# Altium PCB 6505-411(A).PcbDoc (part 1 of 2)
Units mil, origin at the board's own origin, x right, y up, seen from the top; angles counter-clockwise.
Board outline 1549.7 x 1971.6 mil, 4 copper layers (Top Layer, Mid-Layer 1, Mid-Layer 2, Bottom Layer); 80 components, 57 nets, 309 pads, 377 vias.
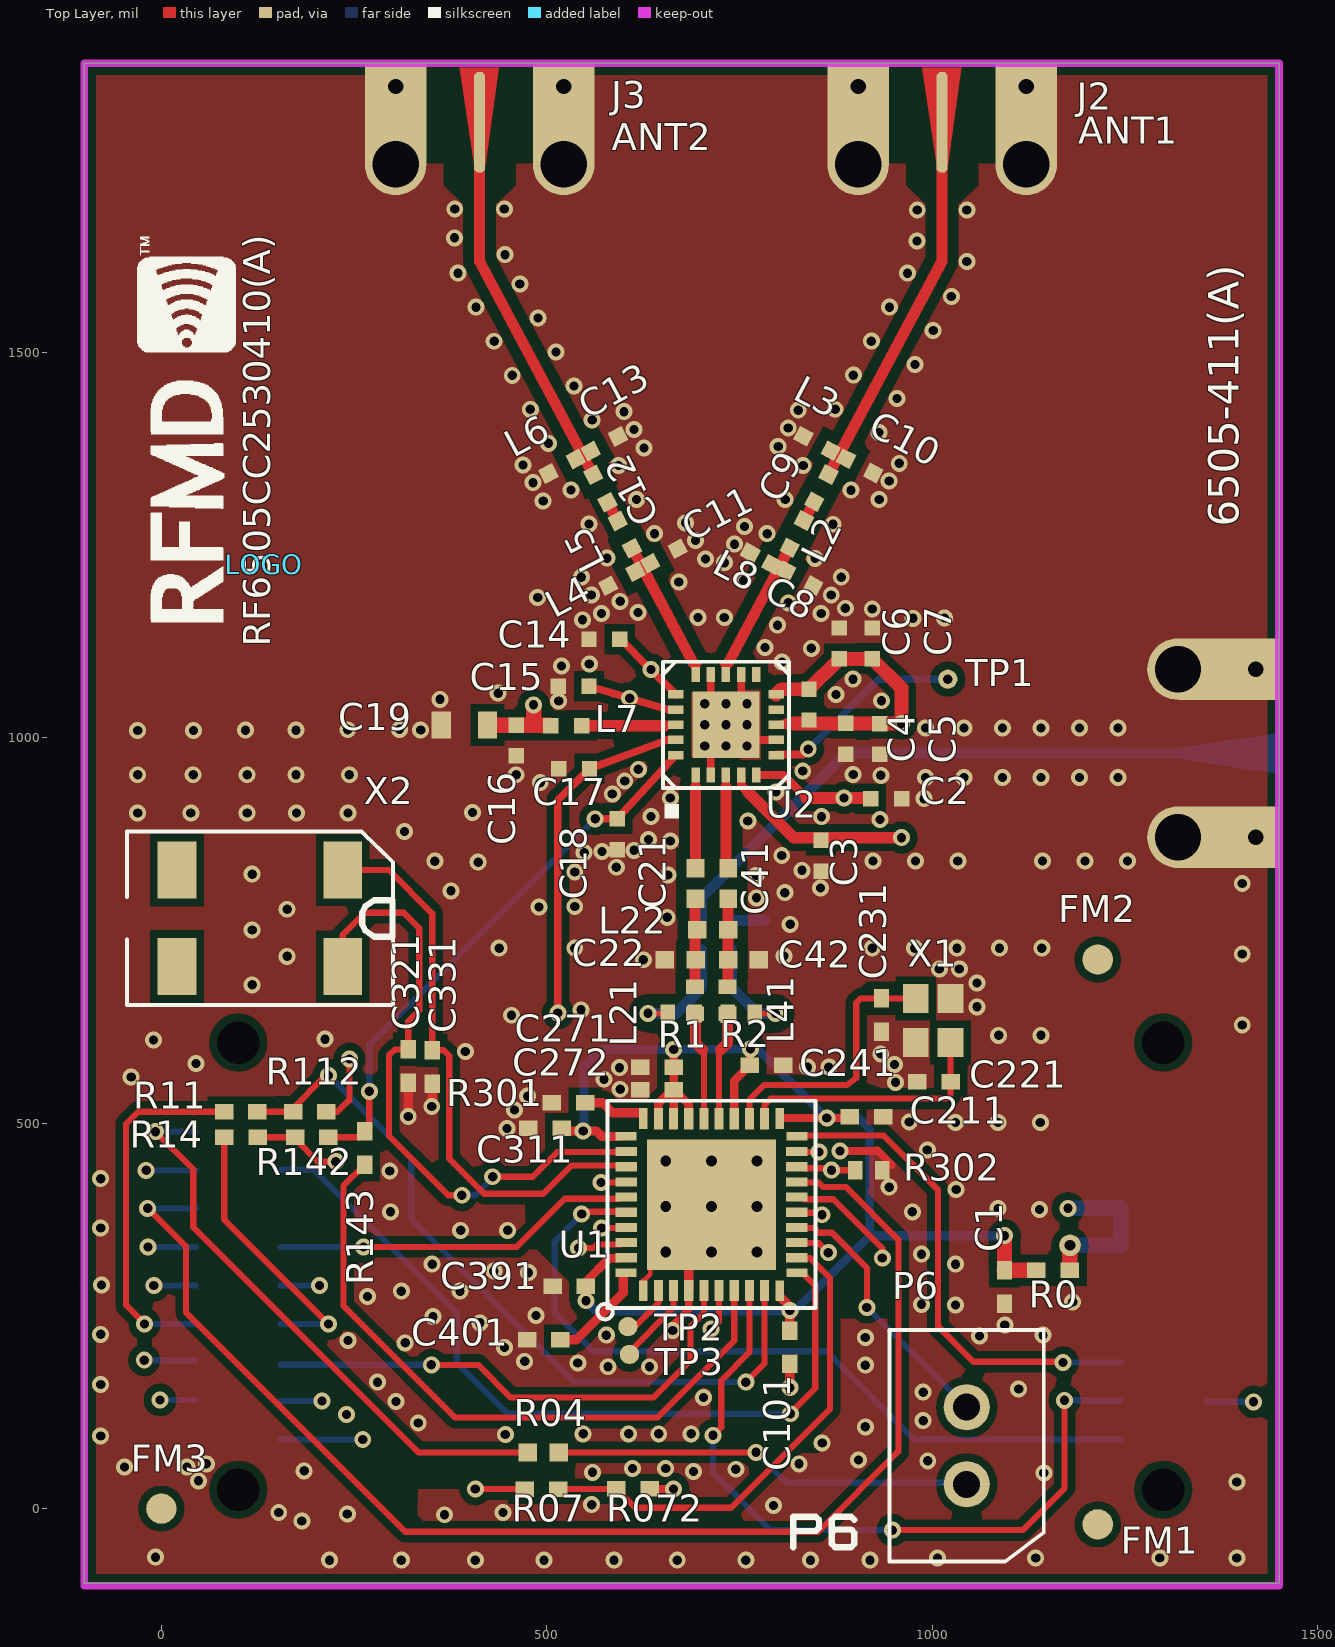
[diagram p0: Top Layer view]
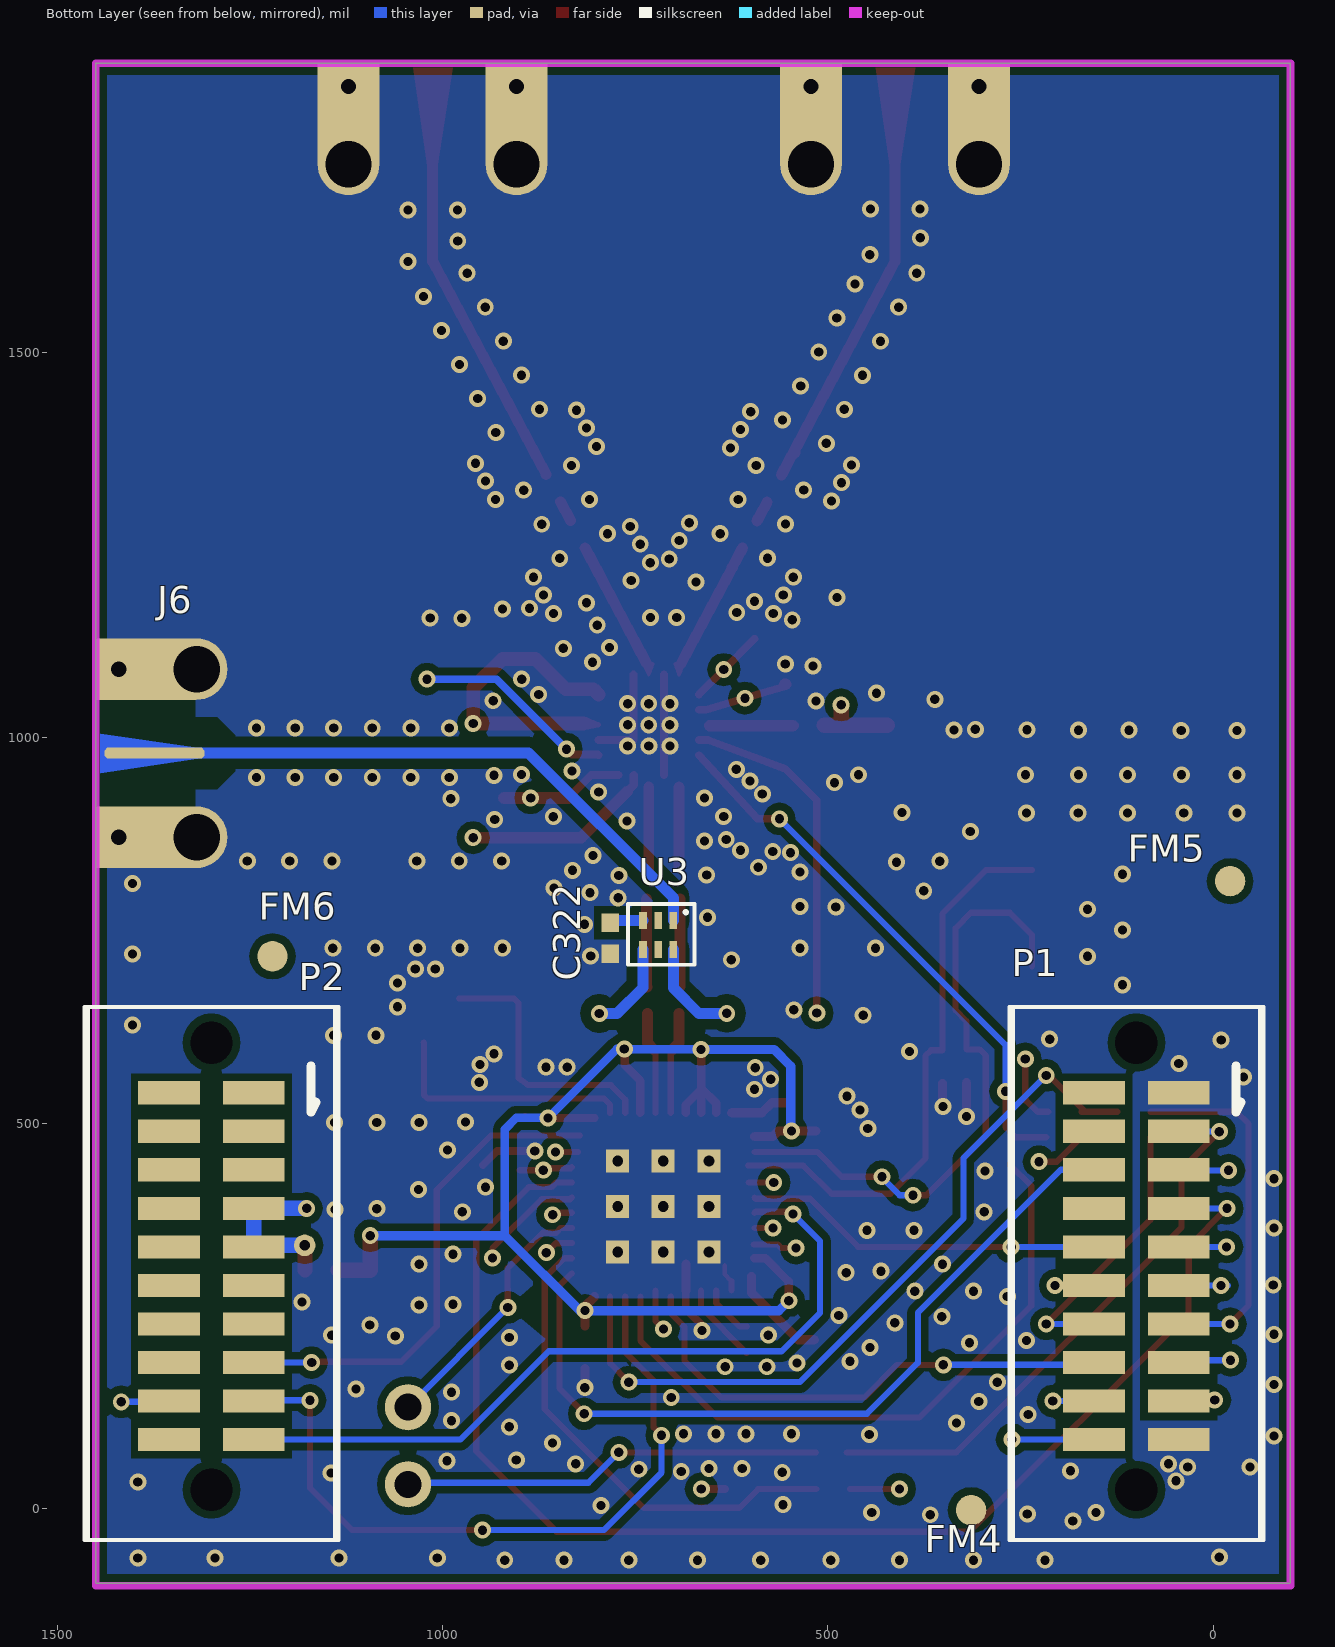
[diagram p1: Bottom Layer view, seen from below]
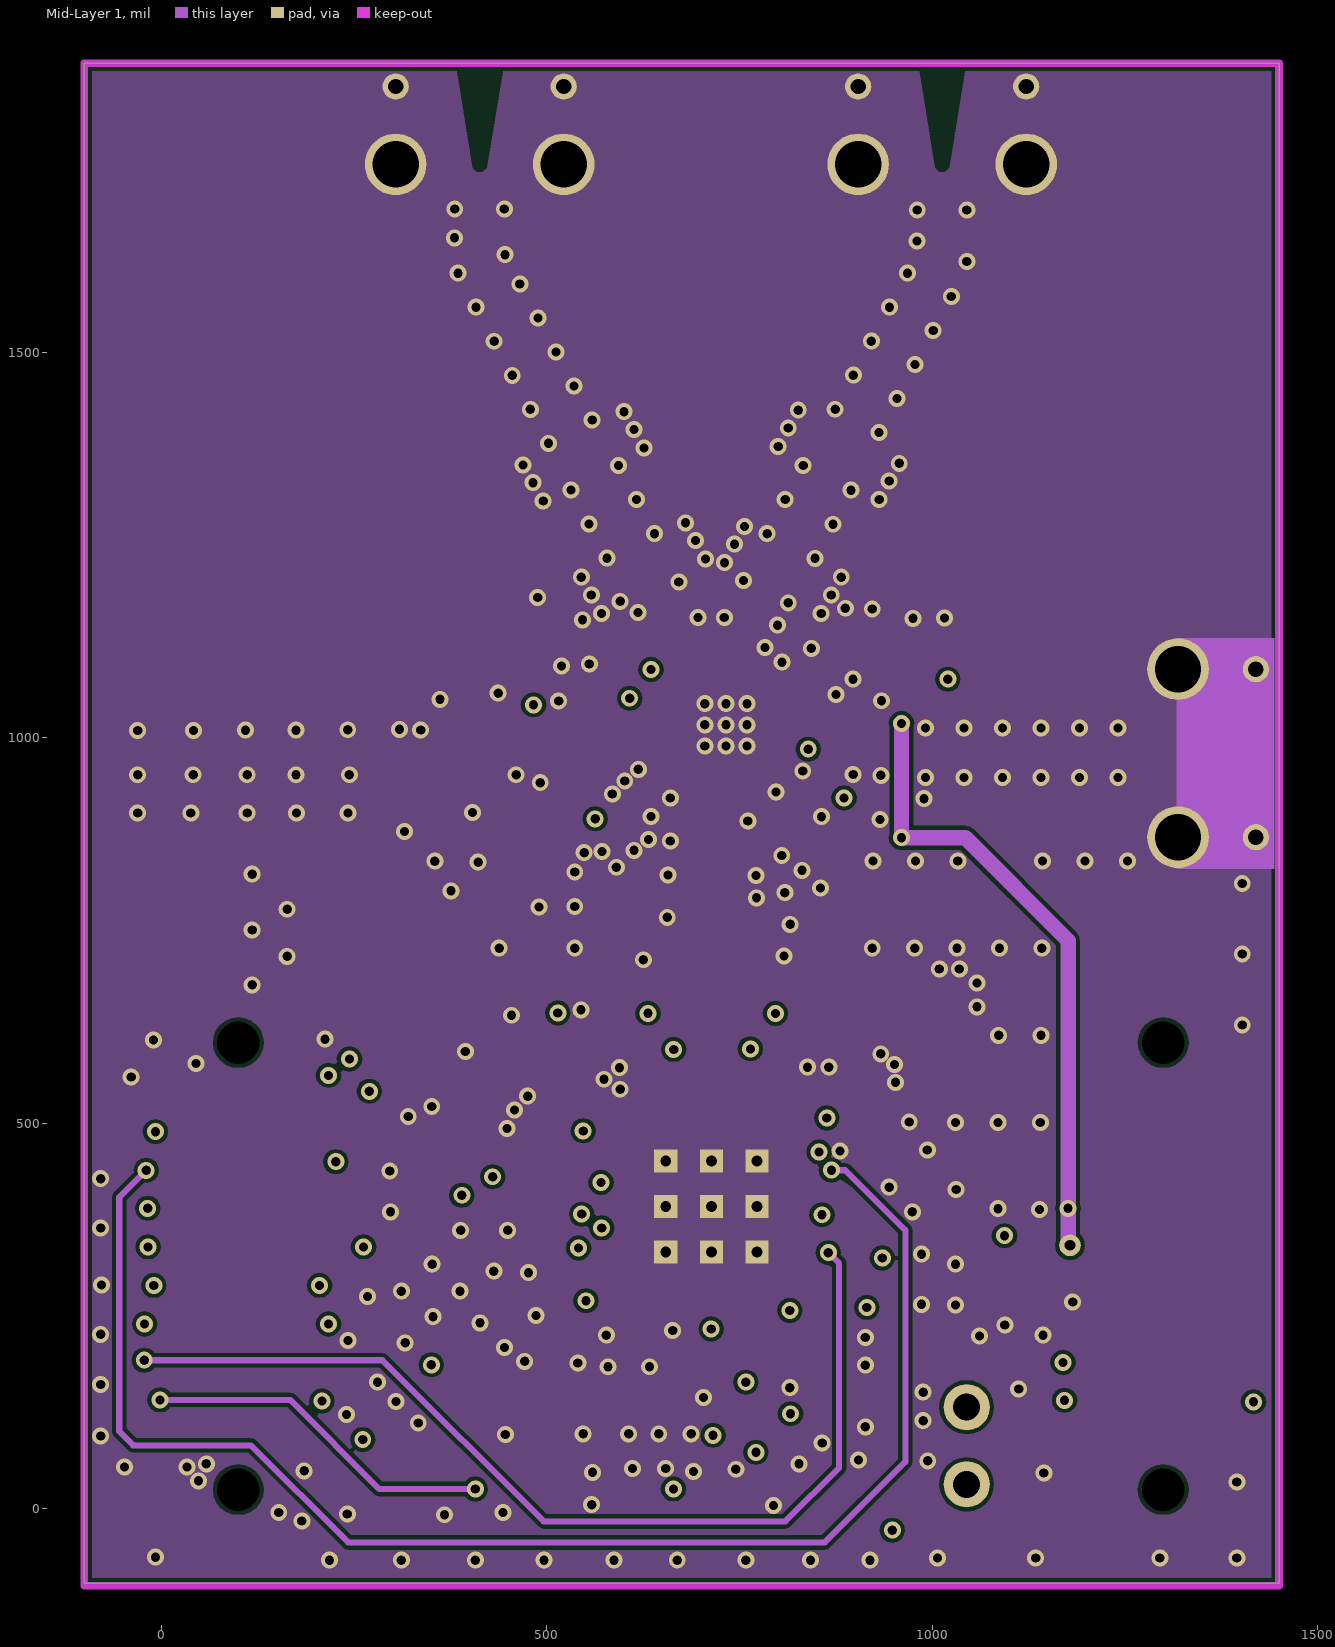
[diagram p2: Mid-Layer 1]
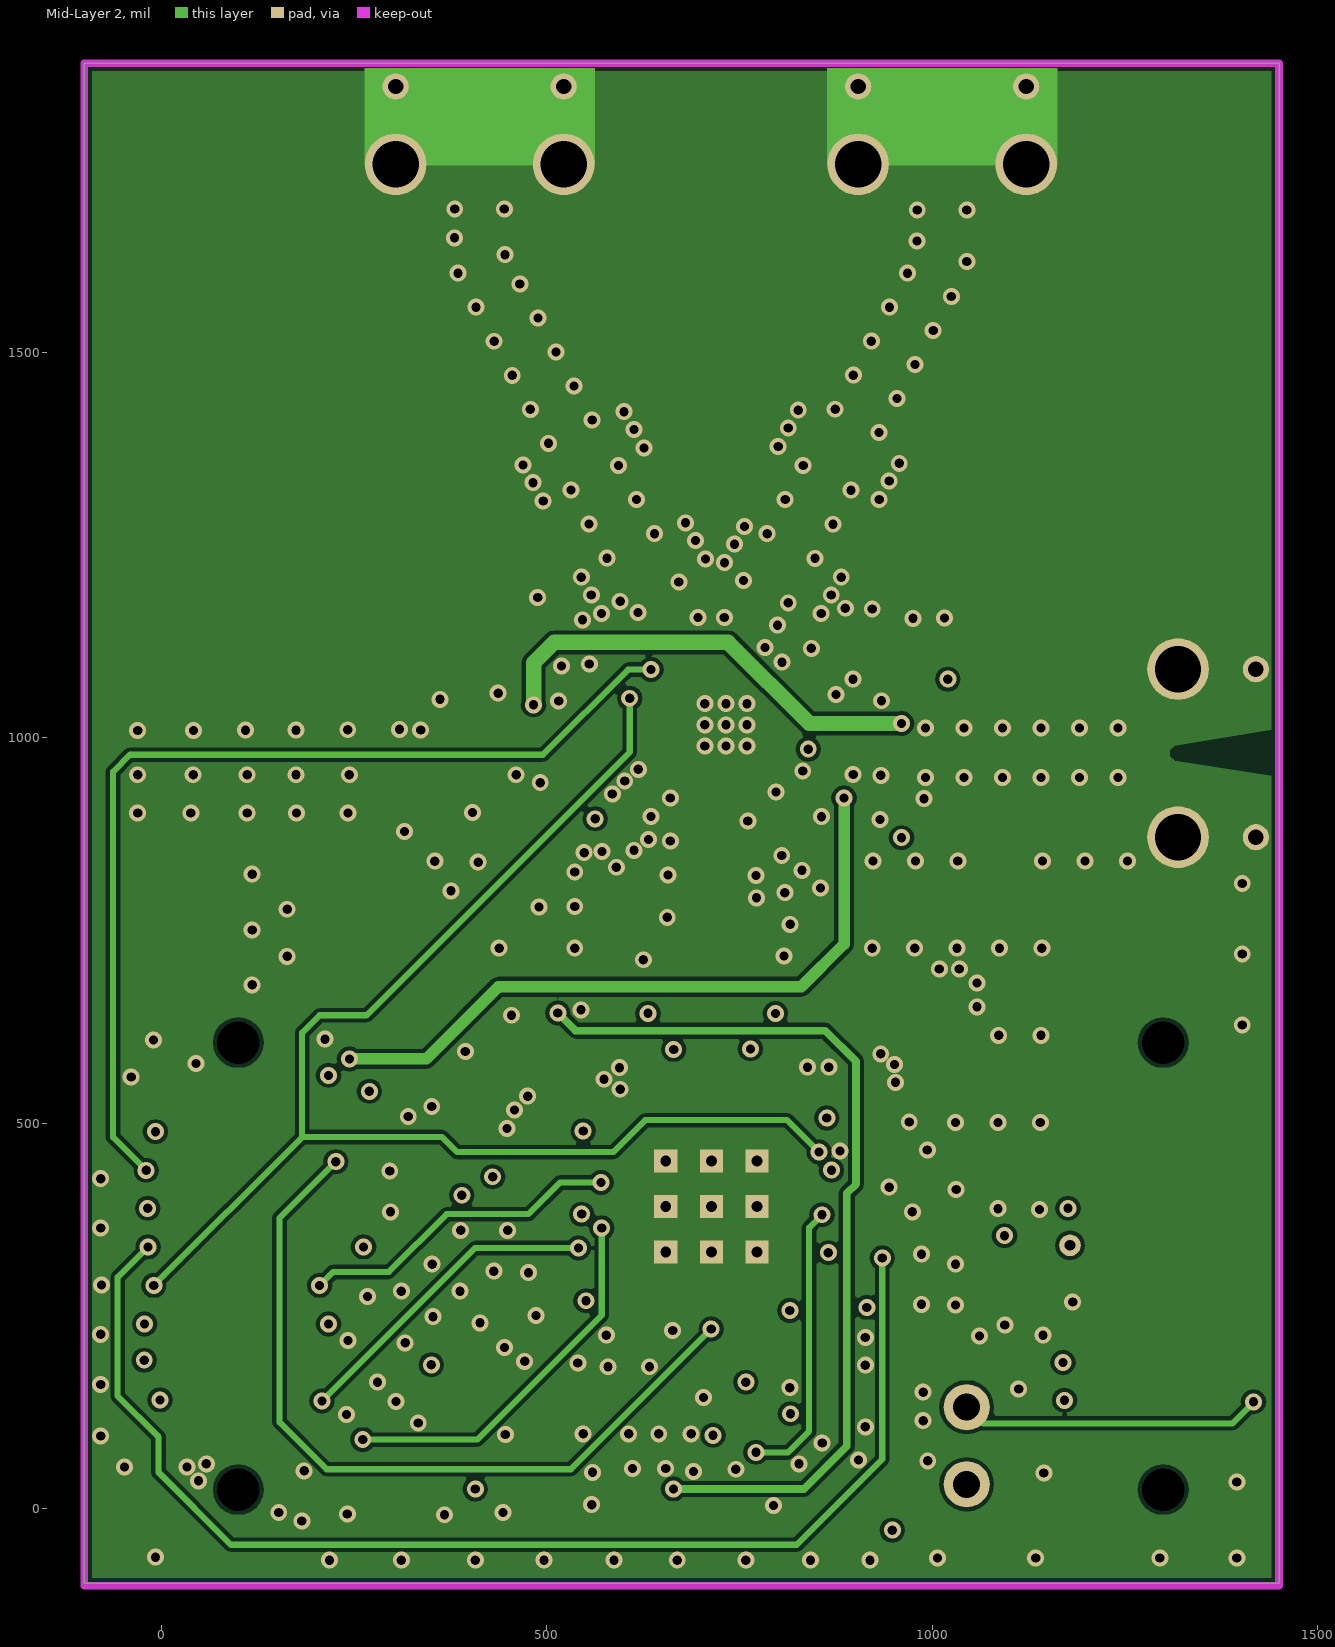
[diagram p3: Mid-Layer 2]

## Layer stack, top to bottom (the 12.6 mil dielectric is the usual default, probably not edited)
Top Layer: signal copper 1.4
Dielectric: core 12.6, FR-4, Dk 4.8
Mid-Layer 1: signal copper 1.4
Dielectric: prepreg 12.6, FR-4, Dk 4.8
Mid-Layer 2: signal copper 1.4
Dielectric: core 12.6, FR-4, Dk 4.8
Bottom Layer: signal copper 1.4

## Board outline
-99.7,-96.6 1450,-96.6 1450,1875 -99.7,1875

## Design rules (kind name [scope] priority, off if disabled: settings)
Clearance Connectors [IsTrack and IsKeepout vs (HasFootprintPad('HDR_*','*') or HasFootprint('SMA_008_MABDC_G1_VIPER')or HasFootprint('SMA_008_MABDC_G1_VIPER_BS') or IsFill)] p1: gap=0
Clearance Clearance_2 [((InPoly)) And InNet('GND') vs HasFootprintPad('SMA_008_MABDC_G1_VIPER','1')or HasFootprintPad('SMA_008_MABDC_G1_VIPER_BS','1')] p2: gap=40
Clearance Clearance_1 [InPoly AND InNet('GND') and (OnLayer('top layer') or OnLayer('Bottom Layer')) vs InNetClass('RF_TRACES')] p3: gap=14
Clearance [InPoly AND InNet('GND') And (OnLayer('Bottom Layer') or OnLayer('Top Layer'))] p4: gap=10
Clearance Clearance_4 [All] p5: gap=5
ComponentClearance [All] p1: gap=8 collisioncheckmode=3 verticalgap=10 showdistances=FALSE
FabricationTestPointUsage TestPointUsage [All] p1: valid=0 allowmultiple=FALSE
FabricationTestpoint Testpoint [All] p1: side=3 testpointundercomponent=TRUE minsize=40 maxsize=100 preferedsize=60 minholesize=20 maxholesize=40 preferedholesize=32 testpointgrid=1 allowsidetop=TRUE allowsidebottom=TRUE usegrid=TRUE gridtolerance=0.01
HoleSize [All] p1: absolutevalues=TRUE maxlimit=125 minlimit=8 maxpercent=80.000 minpercent=20.000
PlaneConnect [All] p1: planeconnectstyle=Direct reliefexpansion=20 reliefentries=4 reliefconductorwidth=10 reliefairgap=10
PolygonConnect [All] p1: connectstyle=Direct reliefconductorwidth=10 reliefentries=4 polygonreliefangle="90 Angle"
RoutingLayers [All] p1: top layer_v5=TRUE mid layer 1_v5=FALSE mid layer 2_v5=FALSE bottom layer_v5=TRUE
RoutingVias [All] p1: holewidth=8 width=20 viastyle="Through Hole" minholewidth=8 minwidth=20 maxholewidth=28 maxwidth=50
ShortCircuit [IsKeepOut vs HasFootprintPad('SMA_008_MABDC_G1_VIPER','*') Or HasFootprintPad('HDR_*','*') or HasFootprintPad('SMA_008_MABDC_G1_VIPER_BS','*')or (IsPolygon and OnTopLayer)] p1: allowed=TRUE
SilkscreenOverComponentPads [All] p1: minsilkscreentomaskgap=10
SolderMaskExpansion [All] p1: expansion=4
Width [All] p1: maxlimit=100 minlimit=5 preferedwidth=14.25
20 further rules are at their usual default settings.

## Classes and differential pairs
net class RF_TRACES: NetC8_1 NetC9_1 NetC9_2 NetC11_1 NetC12_2 NetC21_1 NetC21_2 NetC41_1 NetC41_2 NetJ6_1 NetL21_1 NetL41_1 NetR1_2 NetR2_2

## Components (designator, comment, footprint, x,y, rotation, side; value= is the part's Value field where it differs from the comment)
C1 "2u2" 0402_TI 1093.8,309.3 r270 top
C2 "0.1uF" 0402(A)#1 940.65,921.41 r180 top
C3 "0.01uF" 0402(A)#2 855.48,846.73 r90 top
C4 "1.0uF" 0402(A)#2 887.49,998.35 r90 top
C5 "180pF" 0402(A)#1 932.41,998.16 r90 top
C6 "1.0uF" 0402(A)#1 879.29,1122.85 r270 top
C7 "180pF" 0402(A)#2 922.61,1122.85 r270 top
C8 "0.8pF" 0402(A)#3 828.26,1207 r331.8 top
C9 "1.5pF" 0402(A)#3 856.19,1323.99 r62.24 top
C10 "2.4pF" 0402(A)#3 905.85,1352.92 r332.24 top
C11 "0.8pF" 0402(A)#3 652.05,1235.9 r27.76 top
C12 "1.5pF" 0402(A)#3 569.52,1323.43 r117.65 top
C13 "2.4pF" 0402(A)#3 574.8,1381.44 r28.09 top
C14 "1.0uF" 0402(A)#1 574.44,1127.77 r0 top
C15 "1.0uF" 0402(A)#2 534.43,1067.26 r0 top
C16 "0.01uF" 0402(A)#1 460.71,996.23 r90 top
C17 "0.1uF" 0402(A)#1 535.12,959.68 r0 top
C18 "0.1uF" 0402(A)#1 591.71,874.73 r90 top
C19 "4.7uF" 0603(A) 393.2,1016.57 r0 top
C21 "1.0pF" 0402_T1_2#1 693.1,791.1 r90 top
C22 "DNI" 0402_T1_2#1 693.1,712.1 r180 top
C41 "1.0pF" 0402_T1_2#1 735.3,791.1 r90 top
C42 "DNI" 0402_T1_2#1 735.3,712.1 r0 top
C101 "100n" 0402_TI 815.3,231.1 r270 top
C211 "100n" 0402_TI 893,508.2 r0 top
C221 "27pF" 0402_TI 1023.9,554.1 r180 top
C231 "27pF" 0402_TI 934.3,662 r270 top
C241 "100n" 0402_TI 763.6,575.4 r0 top
C271 "100n" 0402_TI 664.6,572.9 r180 top
C272 "220pF" 0402_TI 664.9,543.6 r180 top
C311 "100n" 0402_TI 519.3,493.7 r180 top
C321 "15pF" 0402_TI 320.3,595.8 r270 top
C322 "DNI" 0402_T1_2#2 782.3,760.1 r270 bottom
C331 "15pF" 0402_TI 351.5,594.8 r270 top
C391 "1uF" 0402_TI 550.8,288.7 r180 top
C401 "1uF" 0402_TI 474.49,219.08 r0 top
FM1 "FID_TI" FID_TI 1214.8,-20.4 r0 top
FM2 "FID_TI" FID_TI 1214.8,712.38 r0 top
FM3 "FID_TI" FID_TI 0,0 r0 top
FM4 "FID_TI" FID_TI 314.3,-1.9 r180 bottom
FM5 "FID_TI" FID_TI -21.7,814.1 r180 bottom
FM6 "FID_TI" FID_TI 1220.6,716.58 r180 bottom
J2 "ANT1" SMA_008_MABDC_G1_VIPER 1013,1875 r270 top
J3 "ANT2" SMA_008_MABDC_G1_VIPER 413,1875 r270 top
J6 "SMA" SMA_008_MABDC_G1_VIPER_BS 1450,980.08 r180 bottom
L2 "3.3nH" 0402(A)#3 824.39,1264.26 r242.15 top
L3 "1.5nH" 0402(A)#3 850.85,1381.95 r152.12 top
L4 "DNI" 0402(A)#3 597.33,1206.59 r207.65 top
L5 "3.3nH" 0402(A)#3 601.29,1263.68 r297.85 top
L6 "1.5nH" 0402(A)#3 519.85,1352.31 r207.88 top
L7 "2.2nH" 0402(A)#1 525.71,1016.23 r180 top
L8 "DNI" 0402(A)#4 777.95,1232.53 r151.64 top
L21 "5.6nH" 0402_S#1 691.86,642.36 r90 top
L22 "DNI" 0402_T1_2#2 735.3,751.1 r180 top
L41 "5.6nH" 0402_S#1 734.3,642.1 r90 top
LOGO "RFMDLOGO" RFMD_LOGO 133.79,1225.08 r90 top
P1 "HDR_2X10" 20PIN_SM 99.8,604.6 r180 bottom
P2 "HDR_2X10" 20PIN_SM 1299.8,604.6 r180 bottom
P6 "CON2" PINROW_1X2 1044.8,131.6 r0 top
R0 "1Kohms" 0402_TI 1135.1,309.3 r0 top
R1 "DNI" 0402_S#1 692.04,641.86 r180 top
R2 "DNI" 0402_S#1 734.8,642.28 r0 top
R04 "0ohm" 0402_T1_2#2 515.5,72.9 r180 top
R07 "DNI" 0402_TI 471.6,25.4 r0 top
R11 "DNI" 0402_TI 81.4,514.9 r0 top
R14 "DNI" 0402_TI 81.6,481.9 r0 top
R072 "1Kohm" 0402_TI 633.4,25.6 r180 top
R112 "1Kohm" 0402_TI 214.2,514.9 r180 top
R142 "1Kohm" 0402_TI 216.7,481.9 r180 top
R143 "DNI" 0402_TI 263.9,489.6 r270 top
R301 "56Kohms" 0402_TI 549.8,526.7 r180 top
R302 "1Kohms" 0402_S#2 934.84,438.66 r180 top
TP1 "TP" TP 1020.3,1076.1 r0 top
TP2 "TP" TP 605.3,236.1 r0 top
TP3 "TP" TP 607.3,200.1 r0 top
U1 "MLP_40_6X6" CC2530 713.75,394.4 r0 top
U2 "RF6505" "3.5x3.5 20 pin" 732.47,1016.92 r0 top
U3 "PKG_6L" LDB182 740,762.8 r180 bottom
X1 "CRYSTAL(24MHz to 54MHz)" CRYSTAL_24-54 1001.26,633.44 r90 top
X2 "CRYSTAL(32.768kHz)" CRYSTAL_32.768 20.3,703.6 r0 top

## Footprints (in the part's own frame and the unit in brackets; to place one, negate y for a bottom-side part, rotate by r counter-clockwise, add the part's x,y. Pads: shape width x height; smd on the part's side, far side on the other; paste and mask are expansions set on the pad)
"3.5x3.5 20 pin" [mm]
  rect 0.28x0.5 smd mask+0.051: 1(-1,-1.655) 2(-0.5,-1.655) 3(0,-1.655) 4(0.5,-1.655) 5(1,-1.655) 11(1,1.655) 12(0.5,1.655) 13(0,1.655) 14(-0.5,1.655) 15(-1,1.655)
  rect 0.5x0.28 smd mask+0.051: 6(1.655,-1) 7(1.655,-0.5) 8(1.655,0) 9(1.655,0.5) 10(1.655,1) 16(-1.655,1) 17(-1.655,0.5) 18(-1.655,0) 19(-1.655,-0.5) 20(-1.655,-1)
  rect 2.2x2.2 smd mask+0.051: 21(0,0)
  silkscreen extent -2.08,-3.08 2.08,2.08
20PIN_SM [mil]
  rect 80x30 smd paste-1 mask+2: 1(55,-65) 2(-55,-65) 3(55,-115) 4(-55,-115) 5(55,-165) 6(-55,-165) 7(55,-215) 8(-55,-215) 9(55,-265) 10(-55,-265) 11(55,-315) 12(-55,-315) 13(55,-365) 14(-55,-365) 15(55,-415) 16(-55,-415) 17(55,-465) 18(-55,-465) 20(-55,-515)
  rect 80x30 smd: 19(55,-515)
  round 5 hole 55 mask-3: 21(0,0) 22(0,-580)
  silkscreen extent -165,-646 160,46
0402(A)#1 [mil]
  rect 20x20 smd: 1(-19.65,0.31) 2(20.35,0.31)
0402(A)#2 [mil]
  rect 20x20 smd: 1(-19.65,-0.31) 2(20.35,-0.31)
0402(A)#3 [mil]
  rect 20x20 smd: 1(-20,0) 2(20,0)
0402(A)#4 [mil]
  rect 21.65x19.68 smd mask+2.5: 1(-15.95,0) 2(15.95,0)
0402_S#1 [mm]
  rect 0.475x0.6 smd: 1(-0.004,-0.009) 2(0.885,-0.009)
0402_S#2 [mm]
  rect 0.475x0.6 smd mask+0.051: 1(-0.004,-0.009) 2(0.885,-0.009)
0402_T1_2#1 [mil]
  rect 24x23 smd: 1(0,0) 2(40,0)
0402_T1_2#2 [mil]
  rect 24x23 smd paste+0: 1(0,0) 2(40,0)
0402_TI [mil]
  rect 24x20 smd paste+0: 1(0,0) 2(43.3,0)
0603(A) [mil]
  rect 25x35 smd mask+3: 1(-30,0) 2(30,0)
CC2530 [mm]
  rect 0.284x0.686 smd: 1(-2.25,-2.835) 10(2.25,-2.835) 21(2.25,2.835) 30(-2.25,2.835)
  rect 0.3x0.696 smd: 2(-1.75,-2.83) 3(-1.25,-2.83) 4(-0.75,-2.83) 5(-0.25,-2.83) 6(0.25,-2.83) 7(0.75,-2.83) 8(1.25,-2.83) 9(1.75,-2.83) 22(1.75,2.83) 23(1.25,2.83) 24(0.75,2.83) 25(0.25,2.83) 26(-0.25,2.83) 27(-0.75,2.83) 28(-1.25,2.83) 29(-1.75,2.83)
  rect 0.686x0.284 smd: 11(2.816,-2.25) 20(2.816,2.25) 31(-2.816,2.25) 40(-2.816,-2.25)
  rect 0.696x0.3 smd: 12(2.811,-1.75) 13(2.811,-1.25) 14(2.811,-0.75) 15(2.811,-0.25) 16(2.811,0.25) 17(2.811,0.75) 18(2.811,1.25) 19(2.811,1.75) 32(-2.811,1.75) 33(-2.811,1.25) 34(-2.811,0.75) 35(-2.811,0.25) 36(-2.811,-0.25) 37(-2.811,-0.75) 38(-2.811,-1.25) 39(-2.811,-1.75)
  rect 4.242x4.293 smd: 41(0,0)
CRYSTAL_24-54 [mm] "Epson"
  rect 0.95x0.85 smd: 1(-0.725,-0.575) 2(0.725,-0.575) 3(0.725,0.575) 4(-0.725,0.575)
CRYSTAL_32.768 [mil]
  rect 50x74 smd paste+0: 1(215,125) 2(215,0) 3(0,0) 4(0,125)
FID_TI [mil]
  round 39.4 smd paste+0: 1(0,0)
LDB182 [mil]
  rect 10x22 smd paste+0: 1(39.4,0) 2(19.7,0) 3(0,0) 4(0,-37.4) 5(19.7,-37.4) 6(39.4,-37.4)
PINROW_1X2 [mil]
  round 60 hole 35: 1(0,-100) 2(0,0)
  silkscreen extent -100,-200 100,100
RFMD_LOGO [mil]
  silkscreen extent -75,37 425,164
SMA_008_MABDC_G1_VIPER [mil]
  oct 130x14.25 smd: 1(76.5,0)
  rect 130x80 smd: 2(65,109) 6(65,-109)
  rect 130x80 smd far side: 3(65,109) 7(65,-109)
  round 34 hole 20: 4(30,109) 8(30,-109)
  round 80 hole 60: 5(131,109) 9(131,-109)
  Top Layer region: 132.7,-7.02 132.7,6.98 5.7,24.98 5.7,-26.02 131.7,-7.02
  Top Layer pour cut-out: -1.44,-106.9 130,-109 130,109 -1.44,111.1
  Mid-Layer 1 pour cut-out: -0.9,-31.3 -0.9,31.7 -0.6,32 135.3,9.9 141.5,3.6 141.5,-3.7 135.1,-9.9
SMA_008_MABDC_G1_VIPER_BS [mil]
  oct 130x14.25 smd: 1(76.5,0)
  rect 130x80 smd: 2(65,109) 6(65,-109)
  rect 130x80 smd far side: 3(65,109) 7(65,-109)
  round 34 hole 20: 4(30,109) 8(30,-109)
  round 80 hole 60: 5(131,109) 9(131,-109)
  Top Layer region: 132.7,-7.02 132.7,6.98 5.7,24.98 5.7,-26.02 131.7,-7.02
  Top Layer pour cut-out: -1.44,-106.9 130,-109 130,109 -1.44,111.1
  Mid-Layer 2 pour cut-out: -0.9,-31.3 -0.9,31.7 -0.6,32 135.3,9.9 141.5,3.6 141.5,-3.7 135.1,-9.9
TP [mil]
  round 25 smd paste+0: 1(0,0)

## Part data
C1 C2 C3 C4 C5 C6 C7 C8 C9 C10 C11 C12 C13 C14 C15 C16 C17 C18 C19 C21 C22 C41 C42 C101 C211 C221 C231 C241 C271 C272 C311 C321 C322 C331 C391 C401: library part CAPACITOR(A), "Capacitor"
J2 J3 J6: library part SMA_008, "SMA Connector"
L2 L3 L4 L5 L6 L7 L8 L21 L22 L41: library part INDUCTOR(A), "Inductor"
LOGO: "RFMD LOGO"
P6: "2 PIN HEADER"
R0 R1 R2 R04 R07 R11 R14 R072 R112 R142 R143 R301 R302: library part RESISTOR(A), "Resistor"
U1: "MLP 40 6X6"
U2: library part "20-LEAD RF6505"
X1: library part "CRYSTAL(A) Epson", "CRYSTAL"
X2: library part CRYSTAL(A), "CRYSTAL"

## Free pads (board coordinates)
  rect 24x20 smd paste+0: 1(621.6,572.9) 1(980.6,554.1) 1(1023.9,554.1)
  rect 30x30 hole 14: 1(654.3,333.1) 1(654.3,392.1) 1(654.3,451.2) 1(713.8,333.1) 1(713.8,392.1) 1(713.8,451.2) 1(772.8,333.1) 1(772.8,392.1) 1(772.8,451.2)
  rect 30x30 smd paste-6.5: 1(654.3,362.6) 1(654.3,421.6) 1(684.3,333.1) 1(684.3,362.6) 1(684.3,392.1) 1(684.3,421.6) 1(684.3,451.2) 1(713.8,362.6) 1(713.8,421.6) 1(743.3,333.1) 1(743.3,362.6) 1(743.3,392.1) 1(743.3,421.6) 1(743.3,451.2) 1(772.8,362.6) 1(772.8,421.6)
  rect 20x20 smd: 1(840.2,1063.1) 2(840.2,1023.1)
  rect 20x24 smd paste+0: 1(934.3,618.7) 1(934.3,662)
  round 28 hole 14: 1(1178.8,341.6)

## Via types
v1: diameter 22, hole 12, Top Layer to Bottom Layer, 281 vias
v2: diameter 22, hole 12, Top Layer to Bottom Layer, tented both sides, 96 vias

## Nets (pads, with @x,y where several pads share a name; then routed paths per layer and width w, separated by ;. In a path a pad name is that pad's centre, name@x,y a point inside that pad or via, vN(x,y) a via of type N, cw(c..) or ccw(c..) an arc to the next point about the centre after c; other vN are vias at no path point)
GND: C1.2 C2.1 C3.1 C4.1 C5.1 C6.1 C7.1 C8.2 C10.2 C11.2 C13.2 C14.1 C15.1 C16.1 C17.1 C18.1 C19.1 C22.2 C42.2 C101.2 C211.2 C221.2 C231.2 C241.2 C271.2 C272.2 C311.2 C321.2 C322.2 C331.2 C391.2 C401.1 J2.2 J2.3 J2.4 J2.5 J2.6 J2.7 J2.8 J2.9 J3.2 J3.3 J3.4 J3.5 J3.6 J3.7 J3.8 J3.9 J6.2 J6.3 J6.4 J6.5 J6.6 J6.7 J6.8 J6.9 L3.2 L4.2 L6.2 L8.2 P1.1 P1.19 pad.1@621.6,572.9 pad.1@654.3,333.1 pad.1@654.3,362.6 pad.1@654.3,392.1 pad.1@654.3,421.6 pad.1@654.3,451.2 pad.1@684.3,333.1 pad.1@684.3,362.6 pad.1@684.3,392.1 pad.1@684.3,421.6 pad.1@684.3,451.2 pad.1@713.8,333.1 pad.1@713.8,362.6 pad.1@713.8,392.1 pad.1@713.8,421.6 pad.1@713.8,451.2 pad.1@743.3,333.1 pad.1@743.3,362.6 pad.1@743.3,392.1 pad.1@743.3,421.6 pad.1@743.3,451.2 pad.1@772.8,333.1 pad.1@772.8,362.6 pad.1@772.8,392.1 pad.1@772.8,421.6 pad.1@772.8,451.2 pad.1@934.3,618.7 pad.1@980.6,554.1 R301.2 R302.1 U1.1 U1.4 U1.41 U2.2 U2.7 U2.12 U2.14 U2.21 X1.2 X1.4 | length 565.7
  Top Layer w6: U1.1@625.2,295 634.1,303.9 U1.41@634.1,315.4
  Top Layer w8: v1(350.8,521.6) v1@351.5,521.6 ; U1.1@625.2,283 U1.1@625.2,295
  Top Layer w10: v1@660.05,234.35 684.3,258.6 U1.4@684.3,283 ; U2.2@712.78,951.76 712.79,1016.92 U2.14@712.79,1082.08 ; U2.12@752.15,1082.08 752.15,1016.92 752.15,997.24 U2.7@797.63,997.24 ; v1(880.3,464.1) 929.2,464.1 947.7,445.6
  Top Layer w12: v1(320.3,508.6) C321.2@320.3,552.5 ; v1@351.5,521.6 C331.2@351.5,551.5 ; U1.4@684.3,283 U1.41@684.3,317.19 ; C101.2@815.2,181.8 815.2,155.4 v1@815.3,155.4
  other v1: 218.3,-66.9 311.3,-66.9 407.3,-66.9 496.3,-66.9 587.3,-66.9 669.3,-66.9 758.3,-66.9 842.3,-66.9 919.3,-66.9 1006.8,-63.9 1134.3,-63.9 1295.3,-63.9 1395.3,-63.9 -7.7,-62.9 182.3,-15.9 367.3,-7.9 241.3,-6.9 152.3,-4.9 443.3,-4.9 794.3,4.1 558.3,5.1 1395.3,34.6 48.3,36.1 1144.8,46.1 559.3,47.1 690.3,48.1 185.3,49.1 745.3,51.1 611.3,52.1 654.3,52.1 -47.7,54.1 33.3,54.1 58.3,58.1 827.3,58.1 994.3,62.1 904.3,63.1 857.3,85.1 -78.7,94.1 446.3,96.1 547.3,97.1 606.3,97.1 645.3,97.1 687.3,97.1 913.3,106.1 333.3,111.1 988.3,114.1 240.3,122.1 304.3,139.1 703.3,144.1 988.3,151.1 1112.3,155.1 815.4,156.9 -78.7,161.1 280.3,164.1 579.3,184.1 633.3,184.1 913.3,186.1 540.3,189.1 471.3,191.1 445.3,209.1 316.3,215.1 242.3,218.1 913.3,222.1 1061.3,224.1 577.3,225.1 1143.8,225 -78.7,226.1 663.3,231.1 1094.3,238.1 413.3,241.1 352.3,249.1 485.9,250.6 1030.3,264.1 986.3,265.1 1182.3,268.1 267.3,275.1 311.3,282.1 387.3,282.1 -77.7,290.1 476.3,306.1 431.3,308.1 351.3,317.1 1030.3,317.1 986.3,330.1 388.3,361.1 449.3,361.1 -78.7,364.1 297.3,385.1 974.3,385.1 1139.3,388.1 1085.3,389.1 1031.19,414.18 944.3,417.1 -78.7,428.1 296.3,438.1 993.7,465.2 448.3,493.1 1030.3,501.1 1085.3,501.1 1140.3,501.1 970.3,501.6 458.3,517.1 475.3,535.1 595.3,544.1 952.3,553.1 574.3,557.1 -39.2,560.1 594.3,572.1 838.3,572.7 865.9,572.7 951.3,576.1 44.8,577.6 933.3,590.1 394.3,593.1 -10.2,608.1 212.3,609.1 1086.3,614.1 1141.3,614.1 1402.3,627.6 454.3,640.1 544.3,647.1 1058.3,651.1 117.8,679.6 1058.3,682.1 1009.3,700.1 1035.3,700.1 625.3,712.1 163.3,716.6 807.8,717.1 1402.3,719.6 438.3,727.1 536.3,727.1 922.3,727.1 977.3,727.1 1032.3,727.1 1087.3,727.1 1142.3,727.1 117.8,750.6 815.8,758.1 656.3,767.1 163.3,777.6 489.8,780.6 536.3,781.1 772.2,792.4 808.8,799.1 375.69,801.58 1402.3,811.1 771.3,821.4 117.8,823.1 536.3,826.1 411.09,838.68 354.8,840 923.3,840.1 978.3,840.1 1033.3,840.1 1143.3,840.1 1198.3,840.1 1253.3,840.1 315.3,878.6 932.3,894.1 -30.7,902.6 38.3,902.6 111.3,902.6 175.3,902.6 242.3,902.6 403.8,903.1 989.3,921.1 991.2,948.48 1041.2,948.48 1091.2,948.48 1141.2,948.48 1191.2,948.48 1241.2,948.48 -30.7,952.1 41.3,952.1 111.3,952.1 174.8,952.1 243.8,952.1 897.5,952.3 933.4,951.4 -30.7,1009.6 41.8,1009.6 109.3,1010 174.8,1010 336.5,1010.3 241.8,1010.5 308.8,1011 991.2,1012.73 1041.2,1012.73 1091.2,1012.73 1141.2,1012.73 1191.2,1012.73 1241.2,1012.73 361.4,1050 502.17,1382.06 930.93,1396.12 558.9,1412.22 478.7,1426.21 874.19,1426.28 954.4,1440.27 535.43,1456.37 455.23,1470.36 897.66,1470.43 977.87,1484.42 511.96,1500.52 431.75,1514.51 921.14,1514.58 1001.34,1528.57 488.49,1544.67 408.28,1558.66 944.61,1558.73 1024.81,1572.72 465.02,1588.82 384.81,1602.81 968.08,1602.88 1044.91,1617.89 445.69,1626.78 980.29,1644.48 380.19,1648.68 980.66,1684.89 1044.91,1684.89 380.66,1686.09 444.91,1686.09
  other v2: 855.3,805.1 657.3,822.1 831.3,828.1 590.3,832.1 804.89,847.28 548.6,851 571.59,852.51 613.3,854.1 660.3,866.1 631.95,868.11 760.8,892 635.3,898.1 856.29,897.78 660.3,922.1 585.1,927.1 797.39,929.78 491.59,941.88 601.2,944.1 460.3,952.1 832.09,956.98 618.8,959.2 705.06,989.51 732.44,989.54 759.82,989.51 705.09,1016.89 732.47,1016.92 759.85,1016.89 705.06,1044.27 732.5,1044.3 759.82,1044.27 515.49,1047.78 934.3,1048.1 875.3,1056.1 437,1058 897.3,1076.1 519.29,1093.08 555.29,1095.78 805.3,1098.1 843.3,1116.1 783.3,1117.1 799.3,1146.1 546.3,1153.1 975.02,1155.01 696.3,1156.1 730.3,1156.1 1016.1,1155.4 570.89,1161.38 856.09,1161.38 618.29,1162.48 922.3,1167.1 887.3,1168.1 813.3,1175.1 595.3,1177.1 488.22,1182.01 557.89,1185.38 869.09,1185.38 671.3,1202.1 755.3,1204.1 544.89,1208.38 882.09,1208.38 730.5,1227.3 705.9,1231.9 578.3,1233.1 847.92,1232.9 743.5,1251.3 692.9,1255.9 639.87,1264.92 785.92,1264.9 756.5,1274.3 554.92,1277.3 871.3,1277.1 679.9,1278.9 495.3,1307.1 616.49,1309.12 809.3,1309.1 931.3,1309.1 894.68,1321.3 531.54,1321.49 482.3,1331.1 944.3,1333.1 593.11,1353.32 832.68,1353.3 469.3,1354.1 957.3,1356.1 626.3,1376.1 800.3,1378.1 613.3,1400.1 813.3,1402.1 600.3,1423.1 826.3,1425.1
HGM: C17.2 R072.1 U2.19 | length 1648.3
  Top Layer w10: v1(514.4,643.1) 514.4,918.92 C17.2@555.46,959.99 655.83,997.29 U2.19@667.31,997.24 ; R072.1@633.4,25.6 v1(664.3,25.6)
  Mid-Layer 2 w10: v1(514.4,643.1) 537.4,620.1 861.3,620.1 901.3,580.1 901.3,421.1 889.3,409.1 889.3,81.1 833.8,25.6 v1(664.3,25.6)
NetC1_1: C1.1 C101.1 C211.1 C241.1 C271.1 C272.1 C311.1 C391.1 R0.1 U1.10 U1.21 U1.24 U1.27 U1.28 U1.29 U1.31 U1.39 | length 1873.2
  Top Layer w10: U1.21@802.4,506.9 v1(863.3,506.9) 891.7,506.9 893,508.1 C211.1@893,508.2
  Top Layer w11: v1(550.8,269.7) C391.1@550.8,288.7 551,288.7 551,294.8 581,324.8 U1.39@595.3,324.8 ; U1.29@644.9,513.6 644.9,525.9 662.6,543.6 C272.1@664.6,543.6 ; v1@664.1,595.8 v1(664.6,595.8) C271.1@664.6,573.5 ; U1.28@664.6,513.6 C272.1@664.6,543.6 ; C271.1@664.9,572.9 664.9,573.9 C271.1@664.6,573.5 ; U1.27@684.3,513.6 684.3,524.3 C272.1@664.9,543.6 C272.1@664.6,543.6 ; U1.24@743.5,513.6 743.5,555.3 C241.1@763.6,575.4 ; C241.1@763.6,576 v1@763.6,598.3 ; C272.1@664.6,543.6 C271.1@664.6,572.9 C271.1@664.6,573.5
  Top Layer w12: C311.1@515.71,490.1 v1(547.3,490.1) 564.2,490.1 571.6,482.7 U1.31@594.9,482.7 ; U1.10@802.7,274.9 815.2,262.4 815.3,262.4 v1(815.3,257.1) C101.1@815.3,237.3
  Top Layer w20: C1.1@1093.7,309.2 C1.1@1093.8,309.3 ; v1(1093.8,354.1) C1.1@1093.8,309.3 ; R0.1@1135.1,309.6 R0.1@1135.1,309.3 C1.1@1093.8,309.3
  Bottom Layer w11: v1(664.6,595.8) v1@764.19,595.8 ; v1(764.19,596.48) 773.72,596.48 v1(863.3,506.9) 904.5,506.9 919.2,492.2 919.2,354.1
  Bottom Layer w12: v1@548.3,490.1 548.3,574.1 570,595.8 v1(664.6,595.8) ; v1(550.8,269.7) 563.9,256.6 821.7,256.6 919.2,354.1 v1(1093.8,354.1)
NetC8_1: C8.1 L2.2 L8.1 U2.13 | length 213.8
  Top Layer w5: 727.48,1095.68 U2.13@732.47,1082.08 ; 732.79,1097.15 U2.13@732.47,1082.08 ; 738.05,1095.6 U2.13@732.47,1082.08
  Top Layer w14.25: 735.44,1096.86 768.68,1159.37 801,1220.16 801.58,1221.26 L2.2@815.05,1246.57
NetC9_1: C9.1 L2.1 | length 27.7
  Top Layer w14.25: L2.1@833.74,1281.94 C9.1@846.88,1306.29
NetC9_2: C9.2 C10.1 J2.1 L3.1 | length 494
  Top Layer w14.25: C9.2@865.58,1341.65 879.06,1367 879.09,1367.05 1012.69,1618.36 ; 1012.79,1617.89 J2.1@1012.79,1798.5
NetC11_1: C11.1 L4.1 L5.2 U2.15 | length 213.1
  Top Layer w5: 687.56,1095.68 U2.15@693.1,1082.08 ; 692.78,1097.15 U2.15@693.1,1082.08 ; 698.01,1095.58 U2.15@693.1,1082.08
  Top Layer w14.25: L5.2@610.83,1246.1 624.11,1221.13 624.29,1220.79 690.17,1096.87
NetC12_1: C12.1 L5.1 | length 27.7
  Top Layer w14.25: C12.1@578.81,1305.71 L5.1@591.94,1281.36
NetC12_2: C12.2 C13.1 J3.1 L6.1 | length 498.8
  Top Layer w14.25: 412.79,1617.89 J3.1@412.79,1798.5 ; 413.18,1617.89 546.78,1366.58 ; L6.1@542.89,1369.31 546.78,1366.58 ; 546.81,1366.52 C12.2@560.29,1341.17 ; 546.81,1366.53 546.78,1366.58
NetC21_1: C21.1 C22.1 L21.2 L22.2 | length 113.9
  Top Layer w14.25: L21.2@692.2,677.2 C21.1@692.2,791.1
NetC21_2: C21.2 U2.1 | length 105.3
  Top Layer w14.25: C21.2@693.1,831.1 693.1,936.44
NetC41_1: C41.1 C42.1 L22.1 L41.2 | length 114.8
  Top Layer w14.25: L41.2@734.64,676.94 735.3,676.94 C42.1@735.3,712.1 L22.1@735.3,751.1 C41.1@735.3,791.1
NetC41_2: C41.2 U2.3 | length 109.3
  Top Layer w14.25: C41.2@732.47,827.1 732.47,936.44
NetC221_1: C221.1 pad.1@1023.9,554.1 U1.22 X1.1 | length 325.9
  Top Layer w8: U1.22@782.7,513.6 782.7,524 790.5,531.9 1019.4,531.9 1023.9,536.4 pad.1@1023.9,554.1 X1.1@1023.9,604.9 X1.1@1024.5,604.9
NetC231_1: C231.1 pad.1@934.3,662 U1.23 X1.3 | length 343.4
  Top Layer w8: U1.23@763,513.6 763,530.8 781.8,549.6 889.4,549.6 901.5,558.9 901.5,656.1 907.4,662 pad.1@934.3,662 X1.3@978.62,661.99
NetC321_1: C321.1 U1.32 X2.2 | length 811.6
  Top Layer w8: X2.2@235.3,703.6 235.3,744.4 264,773.1 314.5,773.1 334.5,753.1 334.5,646.6 320.3,632.4 C321.1@320.3,595.8 303.2,595.8 295.3,587.9 295.3,483.65 372.21,406.6 v1(389.8,406.6) ; v1(429.8,430.6) 481.8,430.6 513.4,462.3 U1.32@595.3,462.6
  Bottom Layer w8: v1(389.8,406.6) 407,406.6 429.8,429.4 v1(429.8,430.6)
NetC322_1: C322.1 U3.3 | length 45
  Bottom Layer w8: C322.1@782.3,760.1 C322.1@782.3,762.8
  Bottom Layer w14.25: U3.3@740,762.8 C322.1@782.3,762.8
NetC331_1: C331.1 U1.33 X2.1 | length 738.9
  Top Layer w8: X2.1@235.3,828.6 294.8,828.6 351.5,771.9 C331.1@351.5,594.8 366.1,594.8 373.5,587.4 373.5,454.1 419,408.6 495.38,408.6 531.88,445.1 U1.33@603.3,445.1
NetC401_2: C401.2 U1.40 | length 127.9
  Top Layer w12: C401.2@517.79,219.08 538.29,219.08 599.2,279.99 U1.40@599.2,301.2
NetJ6_1: J6.1 U3.1 | length 780.5
  Bottom Layer w14.25: U3.1@700.6,762.8 700.6,792.5 888.7,980.6 J6.1@1373.5,980.6
NetL7_1: L7.1 U2.18 | length 108
  Top Layer w15: L7.1@545.36,1015.92 653.36,1015.92
NetL21_1: L21.1 R1.1 U1.26 | length 131.6
  Top Layer w8: U1.26@703.9,513.6 703.9,594.5
  Top Layer w14.25: R1.1@693.2,642.2 693.2,604.2 702.2,595.2
NetL41_1: L41.1 R2.1 U1.25 | length 131.5
  Top Layer w8: U1.25@723.6,513.6 723.6,594.4
  Top Layer w14.25: 725.3,595.1 734.3,604.1 L41.1@734.3,642.1
NetP6_1: P6.1 R04.1 U1.15 | length 938.9
  Top Layer w8: R04.1@515.5,72.9 v1@771.3,72.9 ; U1.15@832.3,383.8 v1@855.6,383.8
  Mid-Layer 2 w8: v1@771.3,72.9 813.1,72.9 840.3,100.1 840.3,364.5 v1(857.1,381.3)
  Bottom Layer w8: v1(771.3,73.1) 810.8,33.6 1042.8,33.6 1042.8,32.4 1043.5,31.6 P6.1@1044.8,31.6
NetR1_2: R1.2 U3.6 | length 159.1
  Top Layer w8: v1(631.3,642.6) 631.3,642.2 R1.2@657.2,642.2
  Bottom Layer w14.25: v1(631.3,642.6) 667.6,642.6 700.6,675.6 U3.6@700.6,725.4
NetR2_2: R2.2 U3.4 | length 147.8
  Top Layer w8: R2.2@769.64,641.94 769.64,642.44 v1(796.64,642.44)
  Bottom Layer w8: v1@796.64,642.24 v1(796.64,642.44)
  Bottom Layer w14.25: U3.4@740,725.4 740,675.8 773.56,642.24 v1@796.64,642.24
NetR07_2: R07.2 R072.2 U1.12 | length 632.2
  Top Layer w8: R07.2@514.9,25.4 R072.2@590.3,25.4 ; R072.2@590.1,25.6 R072.2@590.3,25.4 ; R072.2@590.2,25.7 590.5,25.4 R072.2@590.3,25.4 ; U1.12@832.3,324.8 841.9,324.8 867.3,299.4 867.3,129.1 739.3,1.1 614.6,1.1 R072.2@590.3,25.4
NetR11_2: R11.2 R112.2 U1.9 | length 989.8
  Top Layer w8: R11.2@124.7,514.9 R112.2@166.3,514.9 ; R112.2@170.9,514.9 R112.2@166.3,514.9 ; v1(216.8,562.1) 213.5,562.1 R112.2@166.3,514.9 ; v1(758.3,164.1) 782.7,188.5 U1.9@782.7,275.2
  Bottom Layer w8: v1(216.8,562.1) 324.3,454.6 324.3,376.22 536.27,164.1 v1(758.3,164.1)
NetR14_2: R14.2 R142.2 U1.6 | length 1198.8
  Top Layer w8: R14.2@124.9,481.9 R142.2@173.4,481.9 173.4,479.9 203.14,450.12 v1(226.3,450.1) ; v1(713.3,233.1) 723.6,243.4 U1.6@723.59,283
  Mid-Layer 2 w8: v1(226.3,450.1) 153.3,377.1 153.3,112.1 214.3,51.1 531.3,51.1 v1(713.3,233.1)
NetR143_2: R143.2 U1.7 | length 860.2
  Top Layer w8: R143.2@263.9,446.3 236.3,418.7 236.3,263.1 381.3,118.1 643.2,118.1 743.35,218.03 ; 743.3,218.08 U1.7@743.3,275.2
NetR301_1: R301.1 U1.30 | length 80.3
  Top Layer w12: R301.1@549.8,526.7 572.7,526.7 585.8,513.6 U1.30@624.7,513.6
NetTP1_1: TP1.1 U2.6 | length 263.5
  Top Layer w10: U2.6@797.63,977.55 798.54,978.48 832.38,978.48 v2(839.22,985.32)
  Bottom Layer w10: v2(839.22,985.32) 930,1076.1 v2(1020.3,1076.1)
NetTP2_1: TP2.1 U1.2 | length 68.6
  Top Layer w8: TP2.1@605.3,236.1 614.3,236.1 644.9,266.7 U1.2@644.85,283
NetTP3_1: TP3.1 U1.3 | length 105.6
  Top Layer w8: TP3.1@605.5,201.9 664.6,261 U1.3@664.6,283
P0_0: C15.2 P1.11 U1.19 U2.17 | length 1976.8
  Top Layer w8: U1.19@824.4,462.6 v1(853.3,462.6)
  Top Layer w10: C15.2@554.77,1066.95 586.4,1057.63 v2(607.65,1051.37) 657.72,1036.61 U2.17@667.31,1036.61
  Top Layer w15: C15.2@554.8,1069.4 C15.2@555.9,1069.38
  Mid-Layer 2 w8: v1(-9.81,289.6) 182.69,482.1 ; v2(607.65,1051.37) 607.65,981.45 266.3,640.1 205.3,640.1 182.69,617.49 182.69,482.1 ; v1(853.3,462.6) 811.8,504.1 627.8,504.1 586.3,462.6 383.8,462.6 364.3,482.1 182.69,482.1
  Bottom Layer w8: v1@-18.7,289.6 v1(-9.81,289.6) P1.11@44.8,289.6
P0_1: C14.2 P1.5 R302.2 U1.18 U2.16 | length 3430
  Top Layer w8: U1.18@832.3,442.9 833.6,441.6 v1@871.8,441.6 ; v1(869.3,439.1) 869.4,439 R302.2@900,439
  Top Layer w10: C14.2@595.3,1128.59 v2(635.16,1088.57) U2.16@667.31,1056.29
  Mid-Layer 1 w8: v1(-19.7,438.9) -54.7,403.9 -54.7,100.36 -36.47,82.1 116.3,82.1 242.3,-43.9 860.8,-43.9 965.3,60.6 965.3,361.1 887.3,439.1 v1(869.3,439.1)
  Mid-Layer 2 w8: v1(-19.7,438.9) -62.7,481.9 -62.7,956.1 -40.7,978.1 495.1,978.1 605.57,1088.57 v2(635.16,1088.57)
  Bottom Layer w8: v1(-19.7,438.9) P1.5@44.8,438.9
P0_2: P1.7 U1.17 | length 1730.6
  Top Layer w8: v1(-17.7,389.6) 32.01,339.93 32.04,254.28 316.46,-29.9 852,-29.9 956.3,74.4 956.3,349.1 888.3,417.1 858.5,417.1 854.1,421.5 ; U1.17@832.3,423.2 852.47,423.13
  Bottom Layer w8: v1(-17.7,389.6) P1.7@44.8,389.6
P0_3: P1.9 U1.16 | length 1820.6
  Top Layer w8: U1.16@832.3,403.5 834.4,401.4 871.6,401.4 935.3,337.7 v1(935.3,325.1)
  Mid-Layer 2 w8: v1(-17.2,339.6) -56.7,300.1 -56.7,146.1 -3.7,93.1 -3.7,47.1 90.3,-46.9 824.3,-46.9 935.3,64.1 v1(935.3,325.1)
  Bottom Layer w8: v1(-17.2,339.6) P1.9@44.8,339.6
P0_4: P1.3 R04.2 | length 752
  Top Layer w8: v1(-7.7,489.1) 41.3,440.1 41.3,365.1 333.5,72.9 R04.2@475.5,72.9
  Bottom Layer w8: v1(-7.7,489.1) P1.3@44.8,489.1
P0_5: P2.18 P6.2 U1.14 | length 811.8
  Top Layer w8: U1.14@832.3,364.2 846.68,364.12 852.76,357.96 870.06,357.86 915.6,311.79 v1(915.3,261.1) ; v1@1416.8,137.6 v1(1416.8,138.6)
  Mid-Layer 2 w8: P6.2@1044.8,131.6 1065.8,110.6 1389.8,110.6 v1@1416.8,137.6
  Bottom Layer w8: v1(915.3,261.1) P6.2@1044.8,131.6 P6.2@1044.8,150.6 ; P2.18@1355.8,138.6 v1(1416.8,138.6)
P0_6: P1.15 U1.13 | length 1406.9
  Top Layer w8: U1.13@832.3,344.5 846,344.4 853,344.4 v1(865.3,332.1)
  Mid-Layer 1 w8: v1(-22.2,192.6) 286.8,192.6 496,-16.6 809.6,-16.6 879.3,53.1 879.3,318.1 v1(865.3,332.1)
  Bottom Layer w8: v1(-22.2,192.6) P1.15@44.8,192.6
P0_7: P1.17 R07.1 | length 567.7
  Top Layer w8: v1(407.3,25.4) R07.1@471.6,25.4
  Mid-Layer 1 w8: v1(-1.7,141.1) 167.3,141.1 283,25.4 v1(407.3,25.4)
  Bottom Layer w8: v1(-1.7,141.1) P1.17@44.8,141.1
P1_0: P1.6 U1.11 | length 1033.8
  Top Layer w8: v1(816.3,123.1) 815.3,123.1 848.3,156.1 848.3,289.1 U1.11@832.3,305.1
  Bottom Layer w8: P1.6@154.8,439.6 197.8,439.6 383.3,254.1 383.3,189.34 449.5,123.1 v1(816.3,123.1)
